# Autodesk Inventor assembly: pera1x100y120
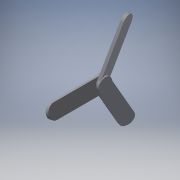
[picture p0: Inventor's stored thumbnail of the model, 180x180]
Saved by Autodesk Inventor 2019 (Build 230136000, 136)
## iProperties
Created: 2020-08
Part Number: pera1x100y120
Material: 一般
Document SubType Name: Assembly
Designer: kikut
Author: kikut
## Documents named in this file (2)
- F:\openFOAM\bathrobo\bathrobo00\oversetmeshpera1\CAD\pera1x100y120.iam
- F:\openFOAM\bathrobo\bathrobo00\oversetmeshpera1\CAD\pera01.ipt
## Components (1 placed, 1 different names)
1. pera01:1 — メイト:1, メイト:2
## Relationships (2: Mate 2)
- メイト:1 [Mate]: pera01:1
- メイト:2 [Mate]: pera01:1
